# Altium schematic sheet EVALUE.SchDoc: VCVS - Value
size A; DocumentNumber: 1; SheetNumber: 1; SheetTotal: 1
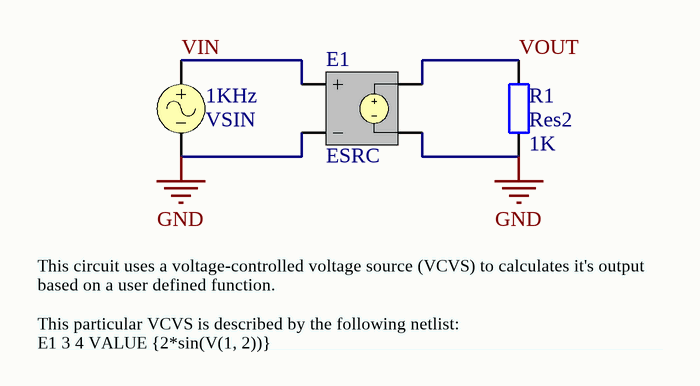
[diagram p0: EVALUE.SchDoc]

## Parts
1KHz  VSIN
E1  ESRC
R1  Res2  value 1K  [AXIAL-0.4]

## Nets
GND: 1KHz.2 E1.2(NC-) E1.4(N-) R1.1
VIN: 1KHz.1 E1.1(NC+)
VOUT: E1.3(N+) R1.2

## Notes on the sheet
- This circuit uses a voltage-controlled voltage source (VCVS) to calculates it's output based on a user defined function.
  This particular VCVS is described by the following netlist:
  E1 3 4 VALUE {2*sin(V(1, 2))}

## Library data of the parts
1KHz = VSIN: Sinusoidal Voltage Source; Note: PCB Footprint - Not required
E1 = ESRC: Voltage Controlled Voltage Source; Note: PCB Footprint - Not required; Sim Note: Enter gain into gain field
R1 = Res2: Resistor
